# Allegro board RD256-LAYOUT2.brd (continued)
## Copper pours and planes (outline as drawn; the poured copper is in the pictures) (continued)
VGATE_A on BOTTOM: 33.05,45.25 32.92,45.28 32.83,45.38 32.8,45.5 32.8,48.55 32.81,48.61 32.87,48.72 33.5,49.35 33.54,49.42 33.55,49.5 33.55,50.76 33.56,50.8 33.58,50.83 34.5,51.75 34.55,51.79 34.68,51.83 35.27,51.83 35.4,51.86 35.45,51.9 35.83,52.27 35.88,52.35 35.9,52.45 35.9,55.15 35.9,55.2 35.87,55.28 35.87,55.4 35.84,55.52 35.8,55.57 35.43,55.95 35.41,55.98 35.4,56.02 35.4,56.75 35.38,56.83 35.27,56.92 35.25,56.98 35.25,60.5 35.27,60.59 35.32,60.67 35.58,60.93 35.66,60.98 35.75,61 35.84,61 36.67,61.35 37.5,61 39.2,61 39.29,60.98 39.37,60.93 39.63,60.67 39.68,60.59 39.7,60.5 39.7,50.73 40.37,50.05 40.39,50.02 40.4,49.98 40.4,48.89 40.39,48.85 40.37,48.82 39.67,48.12 39.62,48.08 39.5,48.05 35.7,48.05 35.58,48.02 35.53,47.98 35.17,47.62 35.11,47.51 35.1,47.45 35.1,45.5 35.07,45.38 34.98,45.28 34.85,45.25
VGATE_B on TOP: 59.42,0.61 59.4,0.61 58.98,0.73 58.64,1 57.2,1 57.08,1.03 56.98,1.12 56.95,1.25 56.95,3.45 56.94,3.57 56.9,3.73 56.9,5.1 56.91,5.16 56.97,5.27 56.98,5.28 57.04,5.39 57.05,5.45 57.05,6.9 57.06,6.93 57.08,6.97 57.48,7.36 57.54,7.48 57.55,7.54 57.55,8.9 57.56,8.96 57.62,9.07 59.47,10.92 59.5,10.94 59.54,10.95 68.55,10.95 68.67,10.92 68.77,10.82 68.8,10.7 68.8,6.45 68.77,6.33 68.67,6.23 68.55,6.2 61.4,6.2 61.27,6.17 61.18,6.08 61.15,5.95 61.15,1.83 61.14,1.76 61.08,1.65 60.33,0.91 60.02,0.7 59.66,0.61 59.64,0.61
VGATE_B on BOTTOM: 58.5,1 58.43,1.03 58.4,1.1 58.4,4.65 58.43,4.78 58.52,4.87 58.65,4.9 61.05,4.9 61.93,5.78 61.99,5.89 62,5.95 62,7.27 61.97,7.4 61.93,7.45 61.38,8 61.36,8.03 61.35,8.07 61.35,10 61.38,10.12 61.48,10.22 61.6,10.25 66.75,10.25 66.93,10.32 67,10.5 67,13.75 67.01,13.81 67.07,13.92 67.92,14.77 67.95,14.79 67.99,14.8 75,14.8 75.06,14.79 75.17,14.73 75.67,14.23 75.69,14.2 75.7,14.16 75.7,12.2 75.67,12.07 75.58,11.98 75.45,11.95 73.6,11.95 73.53,11.98 73.5,12.05 73.5,12.85 73.47,12.97 73.38,13.07 73.25,13.1 68.85,13.1 68.72,13.07 68.63,12.97 68.6,12.85 68.6,8.85 68.59,8.79 68.53,8.68 67.53,7.68 67.5,7.66 67.46,7.65 66.45,7.65 66.33,7.62 66.23,7.53 66.2,7.4 66.2,4 66.19,3.94 66.13,3.83 65.58,3.28 65.55,3.26 65.51,3.25 62.69,3.25 62.67,3.22 61.97,2.52 61.91,2.41 61.9,2.35 61.9,1.1 61.87,1.03 61.8,1
VGD_A on TOP: 40.4,44.75 40.31,44.77 40.23,44.82 40.07,44.98 39.99,45.03 39.9,45.05 38.42,45.05 38.36,45.07 38.32,45.12 38.12,45.4 37.8,45.5 37.38,45.5 37.31,45.49 37.22,45.48 37.07,45.48 37,45.5 36.97,45.58 36.97,46.45 37.04,46.63 37.22,46.7 39.02,46.7 39.05,46.7 39.07,46.68 39.09,46.67 39.1,46.65 39.25,46.5 39.45,46.45 39.53,46.45 39.56,46.44 39.68,46.37 39.79,46.35 41.4,46.35 41.47,46.34 41.54,46.31 41.56,46.29 41.57,46.26 41.6,46.21 41.63,46.16 41.64,46.13 41.65,46.1 41.65,45 41.58,44.82 41.4,44.75
VGD_A on TOP: 47.75,42.9 47.62,42.93 47.53,43.02 47.5,43.15 47.5,44.08 47.6,44.32 47.6,47.25 47.63,47.38 47.73,47.47 47.85,47.5 48.8,47.5 48.92,47.47 49.02,47.38 49.05,47.25 49.05,43.15 49.02,43.02 48.92,42.93 48.8,42.9
VL_A on TOP: 67.85,41.4 67.72,41.43 67.63,41.52 67.6,41.65 67.6,44.71 67.61,44.75 67.63,44.78 67.88,45.03 67.93,45.07 68.05,45.1 71.75,45.1 71.88,45.07 71.97,44.98 72,44.85 72,44.5 72.03,44.38 72.12,44.28 72.25,44.25 74.55,44.25 74.67,44.22 74.77,44.12 74.8,44 74.8,41.69 74.79,41.65 74.77,41.62 74.62,41.47 74.57,41.43 74.45,41.4
VL_A on BOTTOM: outline of 96 points within 47.1,41.4 69.4,60 ; 1 cut-out
VL_A on CONDUCTIVE3: outline of 292 points within 16.4,33.15 69.4,52.05 ; 12 cut-outs
VL_B on TOP: 47.1,2.75 46.97,2.78 46.88,2.88 46.85,3 46.85,3.25 46.85,3.3 46.54,3.97 45.85,4.25 42.75,4.25 42.69,4.26 42.58,4.32 42.42,4.48 42.38,4.53 42.35,4.65 42.35,6.93 42.36,6.97 42.38,7 42.65,7.27 42.68,7.29 42.72,7.3 45.22,7.3 45.35,7.33 45.4,7.37 45.95,7.93 46,7.97 46.13,8 47.31,8 47.35,7.99 47.38,7.97 47.63,7.72 47.74,7.66 47.8,7.65 48.95,7.65 49.02,7.62 49.05,7.55 49.05,6.83 49.04,6.79 49.02,6.76 48.99,6.72 48.92,6.61 48.91,6.55 48.91,4.4 48.88,4.28 48.79,4.18 48.66,4.15 48.39,4.15 47.75,3.89 47.49,3.25 47.49,3 47.46,2.88 47.37,2.78 47.24,2.75
VL_B on TOP: 54.61,13 54.58,13 54.48,13.04 54.4,13.05 54.2,13.05 54.08,13.08 53.98,13.18 53.95,13.3 53.95,14.86 53.96,14.9 53.98,14.93 54.33,15.28 54.38,15.32 54.5,15.35 55.55,15.35 55.61,15.34 55.72,15.28 56.07,14.93 56.09,14.9 56.1,14.86 56.1,14.01 56.1,13.98 56.06,13.88 56.05,13.8 56.05,13.25 56.02,13.12 55.92,13.03 55.8,13
VL_B on BOTTOM: 55.1,13 55.04,13.01 54.93,13.07 54.58,13.42 54.56,13.45 54.55,13.49 54.55,14.45 54.58,14.57 54.67,14.67 54.8,14.7 54.9,14.7 55.01,14.72 55.13,14.79 55.16,14.8 55.85,14.8 56.03,14.73 56.1,14.55 56.1,13.25 56.07,13.12 55.98,13.03 55.85,13
VL_B on BOTTOM: 18.72,7.82 18.67,7.9 18.65,8 18.65,8.3 18.64,8.43 18.6,8.59 18.6,9.85 18.67,10.03 18.85,10.1 18.9,10.1 18.99,10.08 19.07,10.03 19.38,9.72 19.46,9.67 19.56,9.65 20.15,9.65 20.25,9.63 20.33,9.57 20.98,8.92 21.03,8.84 21.05,8.75 21.05,8.07 21.04,8.03 21.02,8 20.91,7.89 20.89,7.87 20.86,7.86 20.59,7.8 20.56,7.8 20.26,7.8 20.16,7.78 20.08,7.73 19.63,7.27 19.45,7.2 19.27,7.27
VL_B on CONDUCTIVE3: outline of 250 points within 18.15,4.45 90.95,19.75 ; 7 cut-outs
N03856 on TOP: 62.6,55.4 62.57,55.52 62.48,55.62 62.35,55.65 61.53,55.65 61.4,55.68 61.31,55.77 61.28,55.9 61.28,56 61.19,56.11 61.05,56.15 59.76,56.15 59.63,56.18 59.54,56.27 59.51,56.4 59.51,57.5 59.54,57.62 59.63,57.72 59.76,57.75 60.51,57.75 61.44,58.89 60.15,59.58 60.05,59.59 60.01,59.67 60.01,60.1 60.04,60.23 60.13,60.32 60.26,60.35 64.3,60.35 64.42,60.32 64.52,60.23 64.55,60.1 64.55,57.5 64.48,57.32 64.3,57.25 63.42,57.25 63.34,57.21 63.3,57.12 63.34,57.04 63.42,57 64.45,57 64.52,56.97 64.55,56.9 64.55,54.9 64.48,54.72 64.3,54.65 62.7,54.65 62.63,54.68 62.6,54.75 ; 1 cut-out
N502328 on TOP: 32.9,1.7 32.77,1.73 32.68,1.82 32.65,1.95 32.65,2.05 32.68,2.17 32.77,2.27 32.9,2.3 33.15,2.3 34.1,3.2 33.24,4.2 32.9,4.2 32.77,4.23 32.68,4.32 32.65,4.45 32.65,6.53 32.69,6.64 32.7,6.7 32.7,8.9 32.77,9.08 32.95,9.15 33.2,9.15 33.52,9.28 33.65,9.6 33.65,11 33.72,11.18 33.9,11.25 36.2,11.25 36.38,11.18 36.45,11 36.45,8.93 36.43,8.83 36.38,8.75 36.13,8.5 36.11,8.45 36.1,8.4 36.1,7.35 36.09,7.29 36.01,7.16 35.89,7.1 35.85,7.1 34.95,7.1 34.83,7.07 34.73,6.97 34.7,6.85 34.7,5.55 34.73,5.42 34.83,5.33 34.95,5.3 35.66,5.3 35.7,5.29 35.73,5.27 36.13,4.87 36.17,4.82 36.2,4.7 36.2,4.45 36.17,4.33 36.08,4.23 35.95,4.2 35.69,4.2 34.74,3.25 35.69,2.3 35.95,2.3 36.08,2.27 36.17,2.17 36.2,2.05 36.2,1.95 36.17,1.82 36.08,1.73 35.95,1.7

Small or netless copper shapes (teardrops, artwork), in the pictures only: 202 on TOP, 195 on BOTTOM, 1 on CONDUCTIVE3

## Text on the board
Ref Des/Silkscreen Bottom: R85 | R150 | R155 | R158 | R156 | P7 | R184 | R152 | C128 | C120 | R129 | R132 | R137 | IC51 | C150 | Q31 | C127 | R125 | C121 | C73 | R143 | C71 | IC23 | C72 | IC27 | R130 | R134 | C152 | C130 | R72 | C70 | P5 | IC22 | R173 | R171 | C146 | IC63 | C91 | R67 | D31 | Q10 | R167 | R165 | C78 | C92 | R89 | R70 | C94 | P4 | D32 | R31 | R30 | R79 | R34 | C85 | IC29 | R82 | C82 | R95 | R94 | R96 | C81 | IC32 | C79 | R102 | R101 | R100 | P11 | Q12 | R104 | R124 | P12 | R33 | R28 | D39 | R84 | D38 | C157 | C156 | C102 | C106 | P2 | P1 | R105 | R106 | R86 | R159 | C101 | C140 | Q29 | R157 | R160 | C89 | R154 | C136 | Q30 | R162 | R161 | C148 | R163 | R168 | R164 | C134 | C142 | IC54 | IC60 | IC55 | R139 | C98 | IC61 | C143 | R169 | C133 | R172 | C151 | R54 | R74 | Q9 | R49 | R48 | IC36 | C87 | IC31 | C96 | R35 | R71 | C103 | Q17 | D25 | Q20 | Q13 | R27 | C110 | R75 | Q11 | R78 | C109 | R122 | R116 | R115 | R121 | R114 | R120 | IC38 | C105
Ref Des/Silkscreen Top: TP42 | R183 | Q28 | TP41 | R126 | R178 | R151 | P7 | Q24 | R177 | R136 | R180 | Q27 | IC25 | C77 | R88 | R91 | R92 | C69 | IC26 | TP48 | R93 | R97 | R98 | TP39 | TP47 | C160 | R127 | C54 | D40 | P5 | C57 | C58 | R128 | D24 | R65 | Q8 | R179 | Q7 | R90 | IC35 | TP30 | P4 | TP32 | CN3 | TP16 | TP19 | R99 | C40 | C66 | C39 | R77 | R66 | C99 | R80 | IC24 | CN2 | C104 | IC30 | C84 | C83 | IC33 | IC46 | C123 | IC49 | R109 | C113 | IC42 | C117 | TP40 | P11 | C86 | R83 | TP44 | P12 | TP46 | TP14 | Q18 | Q19 | IC53 | C124 | R110 | R187 | C126 | IC17 | IC7 | R146 | R56 | R123 | IC47 | C118 | R52 | IC19 | C56 | TP35 | TP37 | R148 | IC14 | C38 | R144 | C37 | P2 | P1 | R119 | C111 | D37 | D27 | D33 | D26 | D35 | D36 | D30 | D28 | D34 | R107 | D29 | C141 | R87 | Q22 | R153 | R182 | D41 | R175 | IC64 | C147 | C116 | R176 | IC65 | C144 | R133 | C76 | C153 | C28 | C154 | Q21 | C138 | IC11 | C90 | R69 | C137 | R181 | R188 | R131 | IC56 | R135 | C135 | IC59 | IC58 | Q23 | IC57 | IC18 | C139 | Q15 | C155 | R68 | Q25 | R73 | C75 | R138 | C95 | Q16 | C93 | R103 | IC34 | C97 | IC15 | C67 | C88 | C80 | IC21 | C100 | Q14 | IC28 | TP12 | IC37 | TP43 | C119 | C74 | IC45 | C122 | IC44 | C114 | C115 | IC43 | IC48 | R76 | R81 | TP45 | R108 | R113 | R140 | R111 | R142 | R117 | R112 | R118 | R147 | C158 | C48 | C131 | IC50 | R51 | R55 | C24 | IC39 | C47 | C159 | C35 | C107 | TP11 | C59 | C132 | TP17 | IC40 | C112 | IC41 | C108
SYMBOL-1-TOP: 1 | 9 | RD256-2
SYMBOL-1-BOTTOM: 1 | 9
